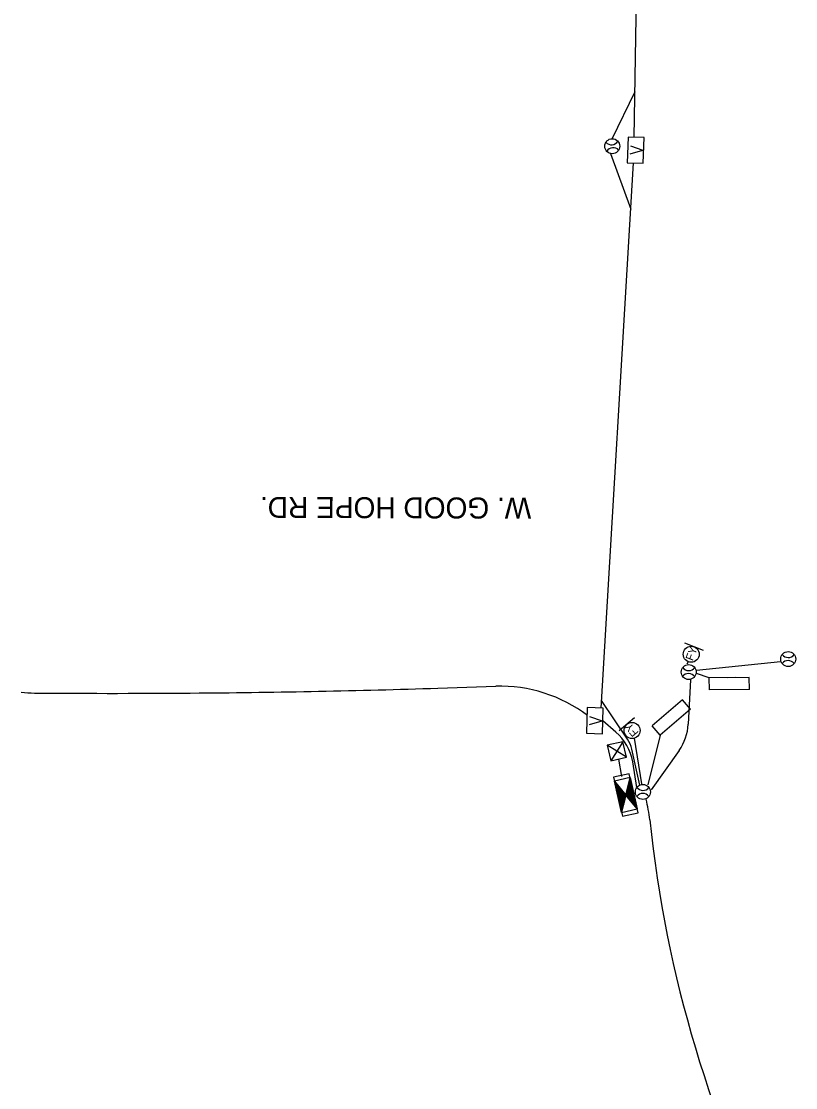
# Model space of a CAD drawing. Extents: x 601562 to 605316, y 332050 to 402250.
# Drawn here: x 603707 to 604094, y 339066 to 339599 of the extents above; entities that cross this region are included whole.
import ezdxf

# ---------------------------------------------------------------- set-up
doc = ezdxf.new("R2010")
doc.units = 0
doc.layers.add('P_FTMS', color=7, linetype='Continuous')
doc.layers.add('P_FTMSConduit', color=7, linetype='Continuous')

# ---------------------------------------------------------------- blocks, each defined once
blk = doc.blocks.new('FCB')
at = {"layer": 'P_FTMS'}
for p, q in [((-48.3, 24.1), (-48, 24.4)), ((-45.5, 22.7), (-47.1, 24.4)), ((-46.9, 23.4), (-46, 24.4)), ((-45.5, 22.8), (-43.9, 24.4)), ((-41.4, 20.7), (-45.1, 24.4)), ((-44.1, 22.1), (-41.8, 24.4)), ((-37.2, 18.6), (-43, 24.4)), ((-42.8, 21.4), (-39.8, 24.4)), ((-41.4, 20.7), (-37.7, 24.4)), ((-33.1, 16.5), (-40.9, 24.4)), ((-40, 20), (-35.6, 24.4)), ((-29, 14.5), (-38.9, 24.4)), ((-38.6, 19.3), (-33.6, 24.4)), ((-37.2, 18.6), (-31.5, 24.4)), ((-24.8, 12.4), (-36.8, 24.4)), ((-35.9, 17.9), (-29.4, 24.4)), ((-20.7, 10.3), (-34.7, 24.4)), ((-34.5, 17.2), (-27.3, 24.4)), ((-33.1, 16.5), (-25.3, 24.4)), ((-16.5, 8.3), (-32.7, 24.4)), ((-31.7, 15.9), (-23.2, 24.4)), ((-12.4, 6.2), (-30.6, 24.4)), ((-30.3, 15.2), (-21.1, 24.4)), ((-29, 14.5), (-19.1, 24.4)), ((-8.3, 4.1), (-28.5, 24.4)), ((-27.6, 13.8), (-17, 24.4)), ((-4.1, 2.1), (-26.4, 24.4)), ((-26.2, 13.1), (-14.9, 24.4)), ((-24.8, 12.4), (-12.9, 24.4)), ((0, 0), (-24.4, 24.4)), ((-24.4, -24.4), (0, 0)), ((-23.5, 11.7), (-10.8, 24.4)), ((1.4, 0.7), (-22.3, 24.4)), ((-22.1, 11), (-8.7, 24.4)), ((-20.7, 10.3), (-6.7, 24.4)), ((2.8, 1.4), (-20.2, 24.4)), ((-19.3, 9.7), (-4.6, 24.4)), ((4.1, 2.1), (-18.2, 24.4)), ((-17.9, 9), (-2.5, 24.4)), ((-16.6, 8.3), (-0.4, 24.4)), ((5.5, 2.8), (-16.1, 24.4)), ((-15.2, 7.6), (1.6, 24.4)), ((6.9, 3.4), (-14, 24.4)), ((-13.8, 6.9), (3.7, 24.4)), ((-12.4, 6.2), (5.8, 24.4)), ((8.3, 4.1), (-12, 24.4)), ((-11, 5.5), (7.8, 24.4)), ((9.7, 4.8), (-9.9, 24.4)), ((-9.7, 4.8), (9.9, 24.4)), ((-8.3, 4.1), (12, 24.4)), ((11, 5.5), (-7.8, 24.4)), ((-6.9, 3.4), (14, 24.4)), ((12.4, 6.2), (-5.8, 24.4)), ((-5.5, 2.8), (16.1, 24.4)), ((-4.1, 2.1), (18.2, 24.4)), ((13.8, 6.9), (-3.7, 24.4)), ((-2.8, 1.4), (20.2, 24.4)), ((15.2, 7.6), (-1.6, 24.4)), ((-1.4, 0.7), (22.3, 24.4)), ((0, 0), (24.4, 24.4)), ((24.4, -24.4), (0, 0)), ((16.6, 8.3), (0.4, 24.4)), ((17.9, 9), (2.5, 24.4)), ((4.1, 2.1), (26.5, 24.4)), ((19.3, 9.7), (4.6, 24.4)), ((20.7, 10.3), (6.7, 24.4)), ((8.3, 4.1), (28.5, 24.4)), ((22.1, 11), (8.7, 24.4)), ((23.4, 11.7), (10.8, 24.4)), ((12.4, 6.2), (30.6, 24.4)), ((24.8, 12.4), (12.9, 24.4)), ((26.2, 13.1), (14.9, 24.4)), ((16.6, 8.3), (32.7, 24.4)), ((27.6, 13.8), (17, 24.4)), ((29, 14.5), (19.1, 24.4)), ((20.7, 10.3), (34.7, 24.4)), ((30.3, 15.2), (21.1, 24.4)), ((31.7, 15.9), (23.2, 24.4)), ((24.8, 12.4), (36.8, 24.4)), ((33.1, 16.6), (25.3, 24.4)), ((34.5, 17.2), (27.3, 24.4)), ((29, 14.5), (38.9, 24.4)), ((35.9, 17.9), (29.4, 24.4)), ((37.2, 18.6), (31.5, 24.4)), ((33.1, 16.6), (40.9, 24.4)), ((38.6, 19.3), (33.5, 24.4)), ((40, 20), (35.6, 24.4)), ((37.2, 18.6), (43, 24.4)), ((41.4, 20.7), (37.7, 24.4)), ((42.8, 21.4), (39.8, 24.4)), ((41.4, 20.7), (45.1, 24.4)), ((44.1, 22.1), (41.8, 24.4)), ((45.5, 22.8), (43.9, 24.4)), ((45.5, 22.8), (47.1, 24.4)), ((46.9, 23.5), (46, 24.4)), ((48.3, 24.1), (48, 24.4)), ((-48, -24.4), (-48.3, -24.1)), ((-47.2, -24.4), (-45.5, -22.8)), ((-45.9, -24.4), (-46.9, -23.5)), ((-43.9, -24.4), (-45.5, -22.8)), ((-45.1, -24.4), (-41.4, -20.7)), ((-41.8, -24.4), (-44.1, -22.1)), ((-43, -24.4), (-37.3, -18.6)), ((-39.7, -24.4), (-42.8, -21.4)), ((-37.7, -24.4), (-41.4, -20.7)), ((-41, -24.4), (-33.1, -16.6)), ((-35.6, -24.4), (-40, -20)), ((-38.9, -24.4), (-29, -14.5)), ((-33.5, -24.4), (-38.6, -19.3)), ((-31.5, -24.4), (-37.2, -18.6)), ((-36.8, -24.4), (-24.8, -12.4)), ((-29.4, -24.4), (-35.9, -17.9)), ((-34.8, -24.4), (-20.7, -10.4)), ((-27.3, -24.4), (-34.5, -17.2)), ((-25.3, -24.4), (-33.1, -16.6)), ((-32.7, -24.4), (-16.6, -8.3)), ((-23.2, -24.4), (-31.7, -15.9)), ((-30.6, -24.4), (-12.4, -6.2)), ((-21.1, -24.4), (-30.3, -15.2)), ((-19, -24.4), (-29, -14.5)), ((-28.5, -24.4), (-8.3, -4.1)), ((-17, -24.4), (-27.6, -13.8)), ((-26.5, -24.4), (-4.1, -2.1)), ((-14.9, -24.4), (-26.2, -13.1)), ((-12.8, -24.4), (-24.8, -12.4)), ((-10.8, -24.4), (-23.4, -11.7)), ((-22.3, -24.4), (1.4, -0.7)), ((-8.7, -24.4), (-22.1, -11)), ((-6.6, -24.4), (-20.7, -10.3)), ((-20.3, -24.4), (2.8, -1.4)), ((-4.6, -24.4), (-19.3, -9.7)), ((-18.2, -24.4), (4.1, -2.1)), ((-2.5, -24.4), (-17.9, -9)), ((-0.4, -24.4), (-16.6, -8.3)), ((-16.1, -24.4), (5.5, -2.8)), ((1.6, -24.4), (-15.2, -7.6)), ((-14.1, -24.4), (6.9, -3.4)), ((3.7, -24.4), (-13.8, -6.9)), ((5.8, -24.4), (-12.4, -6.2)), ((-12, -24.4), (8.3, -4.1)), ((7.8, -24.4), (-11, -5.5)), ((-9.9, -24.4), (9.7, -4.8)), ((9.9, -24.4), (-9.7, -4.8)), ((12, -24.4), (-8.3, -4.1)), ((-7.8, -24.4), (11, -5.5)), ((14.1, -24.4), (-6.9, -3.5)), ((-5.8, -24.4), (12.4, -6.2)), ((16.1, -24.4), (-5.5, -2.8)), ((18.2, -24.4), (-4.1, -2.1)), ((-3.7, -24.4), (13.8, -6.9)), ((20.3, -24.4), (-2.8, -1.4)), ((-1.6, -24.4), (15.2, -7.6)), ((22.3, -24.4), (-1.4, -0.7)), ((0.4, -24.4), (16.6, -8.3)), ((2.5, -24.4), (17.9, -9)), ((26.5, -24.4), (4.1, -2.1)), ((4.6, -24.4), (19.3, -9.7)), ((6.6, -24.4), (20.7, -10.3)), ((28.5, -24.4), (8.3, -4.1)), ((8.7, -24.4), (22.1, -11)), ((10.8, -24.4), (23.4, -11.7)), ((30.6, -24.4), (12.4, -6.2)), ((12.8, -24.4), (24.8, -12.4)), ((14.9, -24.4), (26.2, -13.1)), ((32.7, -24.4), (16.6, -8.3)), ((17, -24.4), (27.6, -13.8)), ((19.1, -24.4), (29, -14.5)), ((34.7, -24.4), (20.7, -10.3)), ((21.1, -24.4), (30.3, -15.2)), ((23.2, -24.4), (31.7, -15.9)), ((36.8, -24.4), (24.8, -12.4)), ((25.3, -24.4), (33.1, -16.6)), ((27.3, -24.4), (34.5, -17.2)), ((38.9, -24.4), (29, -14.5)), ((29.4, -24.4), (35.9, -17.9)), ((31.5, -24.4), (37.2, -18.6)), ((40.9, -24.4), (33.1, -16.6)), ((33.5, -24.4), (38.6, -19.3)), ((35.6, -24.4), (40, -20)), ((43, -24.4), (37.2, -18.6)), ((37.7, -24.4), (41.4, -20.7)), ((39.7, -24.4), (42.8, -21.4)), ((45.1, -24.4), (41.4, -20.7)), ((41.8, -24.4), (44.1, -22.1)), ((43.9, -24.4), (45.5, -22.8)), ((47.2, -24.4), (45.5, -22.8)), ((46, -24.4), (46.9, -23.5)), ((48, -24.4), (48.3, -24.1))]:
    blk.add_line(p, q, dxfattribs=at)
for points in [[(61, 24.4), (-61, 24.4), (-61, -24.4), (61, -24.4)], [(48.8, 24.4), (-48.8, 24.4), (-48.8, -24.4), (48.8, -24.4)], [(48.8, 24.4), (0, 0), (-48.8, 24.4)], [(48.8, -24.4), (-48.8, -24.4), (0, 0)]]:
    blk.add_lwpolyline(points, close=True, dxfattribs=at)
blk = doc.blocks.new('FMB_1')
at = {"layer": 'P_FTMS'}
for p, q in [((24.4, -24.4), (-24.4, 24.4)), ((-24.4, -24.4), (24.4, 24.4))]:
    blk.add_line(p, q, dxfattribs=at)
blk.add_lwpolyline([(24.4, -24.4), (24.4, 24.4), (-24.4, 24.4), (-24.4, -24.4)], close=True, dxfattribs=at)
blk = doc.blocks.new('_U227')
at = {"layer": 'P_FTMS'}
for p, q in [((30.4, 9.4), (-30.6, 8.9)), ((-30.4, -9.4), (-30.6, 8.9)), ((30.6, -8.9), (30.4, 9.4)), ((30.6, -8.9), (-30.4, -9.4))]:
    blk.add_line(p, q, dxfattribs=at)
blk = doc.blocks.new('FFY')
at = {"layer": 'P_FTMS'}
blk.add_line((24.4, -30.5), (24.4, 30.5), dxfattribs=at)
blk.add_circle((0, 0), 24.4, dxfattribs=at)
blk.add_text('FY', height=24.38, dxfattribs=at).set_placement((-18.5, -12.2))
blk = doc.blocks.new('FTMS_FCV')
at = {"layer": 'P_FTMS'}
blk.add_line((12.7, 16.3), (0.6, -21.9), dxfattribs=at)
blk.add_lwpolyline([(39.1, 24.4), (-39.1, 24.4), (-39.1, -24.4), (39.1, -24.4)], close=True, dxfattribs=at)
blk.add_lwpolyline([(-12.1, 16.2), (0.6, -21.9)], dxfattribs=at)

msp = doc.modelspace()

# ---------------------------------------------------------------- linework, layer by layer
at = {"layer": 'P_FTMS'}
for p, q in [((604050.9, 339270.87), (604044.55, 339273.03)), ((604063.92, 339271.03), (604060.26, 339270.77)), ((604026.29, 339242.2), (604020.13, 339217.26))]:
    msp.add_line(p, q, dxfattribs=at)
for centre in [(604002.37, 339536.49), (604090.37, 339280.21), (604040.61, 339273.69), (604017.68, 339213.79)]:
    msp.add_circle(centre, 3.75, dxfattribs=at)
for centre, start, end in [((604001.93, 339540.97), 222.4831, 328.7387), ((604002.81, 339532.01), 42.4831, 148.7387), ((604090.43, 339284.71), 216.2095, 322.4651), ((604040.66, 339278.19), 216.2095, 322.4651), ((604090.32, 339275.71), 36.2095, 142.4651), ((604040.56, 339269.19), 36.2095, 142.4651), ((604017.62, 339209.29), 36.2095, 142.4651), ((604017.73, 339218.29), 216.2095, 322.4651)]:
    msp.add_arc(centre, 3.75, start, end, dxfattribs=at)
at = {"layer": 'P_FTMSConduit'}
for p, q in [((604017.48, 339831.11), (604013.23, 339540.95)), ((604002.29, 339540.14), (604013.85, 339563.83)), ((604001.47, 339532.85), (604011.63, 339505.01)), ((603996.75, 339255.71), (604012.99, 339528.12)), ((604040.41, 339278.84), (604039.71, 339277.59)), ((604044.51, 339274.59), (604086.55, 339278.98)), ((603915.17, 339265.66), (603944.09, 339266.59)), ((604009.96, 339240.22), (603997.07, 339259.43)), ((604004.16, 339243.73), (603997.67, 339249.26)), ((604017.11, 339217.77), (604013.51, 339240.69)), ((604016.13, 339217.17), (604012.15, 339235.11)), ((604005.58, 339230.19), (604007.04, 339221.45)), ((604014.7, 339216.08), (604012.6, 339228.79)), ((604014.11, 339212.97), (604013.06, 339213.13))]:
    msp.add_line(p, q, dxfattribs=at)
for points in [[(604041.5, 339269.79), (604040.35, 339247.65)], [(604035.84, 339234.57), (604021.91, 339214.76)]]:
    msp.add_lwpolyline(points, dxfattribs=at)
for centre, radius, start, end in [((603752.97, 344321.91), 5058.85, 270.48516, 271.83729), ((603946.41, 339194.47), 72.15, 52.7857, 91.8373), ((603713.85, 339313.21), 50, 261.893, 269.5524), ((603752.97, 344321.91), 5058.85, 269.55242, 270.49306), ((604015.39, 339248.95), 25, 324.8835, 357.0207), ((603987.94, 339224.7), 25, 9.3958, 49.5431), ((603997.51, 339231.86), 15, 12.4924, 33.8671), ((603942.04, 339191.57), 79.49, 5.958, 13.4818), ((604640.25, 339264.43), 622.48, 185.95802, 207.38381)]:
    msp.add_arc(centre, radius, start, end, dxfattribs=at)

# ---------------------------------------------------------------- block references
at = {"layer": 'P_FTMS'}
for name, p, xscale, yscale, rotation in [('FTMS_FCV', (604014.13, 339534.5), 0.16404166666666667, 0.16404166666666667, 88.04112391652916), ('FFY', (604041.85, 339282.57), 0.16404166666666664, 0.1640416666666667, 68.87537191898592), ('FTMS_FCV', (603993.67, 339249.39), 0.16404166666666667, 0.16404166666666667, 88.04112391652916), ('_U227', (604031.94, 339250.98), 0.32808333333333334, 0.3280833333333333, 40.12301998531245), ('FFY', (604012.28, 339244.49), 0.16404166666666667, 0.16404166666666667, 130.4251150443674), ('FMB_1', (604004.69, 339234.09), 0.1640416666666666, 0.16404166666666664, 102.94164813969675), ('FCB', (604009.16, 339212.24), 0.1640416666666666, 0.16404166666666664, 102.94164813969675)]:
    msp.add_blockref(name, p, dxfattribs=dict(at, xscale=xscale, yscale=yscale, rotation=rotation))
at = {"layer": 'P_FTMS', "xscale": 0.32808333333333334, "yscale": 0.32808333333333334}
msp.add_blockref('_U227', (604060.93, 339267.95), dxfattribs=at)

# ---------------------------------------------------------------- texts
at = {"layer": 'P_FTMSConduit'}
msp.add_text('W. GOOD HOPE RD.', height=10.5, rotation=179.8354, dxfattribs=at).set_placement((603961.89, 339360.85))

doc.saveas('drawing.dxf')
